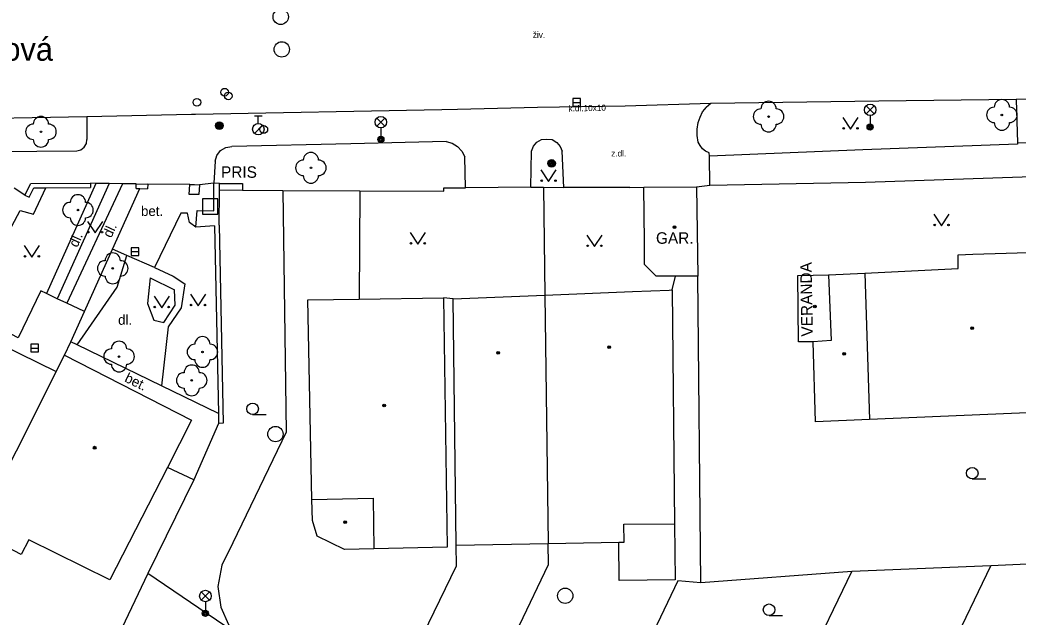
# Model space of a CAD drawing. Extents: x -600309 to -598967, y -1161267 to -1160292.
# Drawn here: x -599902.5 to -599837.4, y -1160659 to -1160620.1 of the extents above; entities that cross this region are included whole.
import ezdxf

# ---------------------------------------------------------------- set-up
doc = ezdxf.new("R2010")
doc.units = 0
for name, color, linetype in [('Level 10', 7, 'Continuous'), ('Level 11', 7, 'Continuous'), ('Level 22', 7, 'Continuous'), ('Level 24', 7, 'Continuous'), ('Level 25', 7, 'Continuous'), ('Level 26', 7, 'Continuous'), ('Level 27', 7, 'Continuous'), ('Level 28', 7, 'Continuous'), ('Level 33', 7, 'Continuous'), ('Level 36', 7, 'Continuous'), ('Level 39', 7, 'Continuous'), ('Level 40', 7, 'Continuous'), ('Level 41', 7, 'Continuous'), ('Level 42', 7, 'Continuous'), ('Level 49', 7, 'Continuous'), ('Level 5', 7, 'Continuous'), ('Level 7', 7, 'Continuous'), ('Level 8', 7, 'Continuous')]:
    doc.layers.add(name, color=color, linetype=linetype)

msp = doc.modelspace()

# ---------------------------------------------------------------- linework, layer by layer
at = {"layer": 'Level 10'}
for points in [[(-599831.42, -1160625.12), (-599837.52, -1160625.25), (-599846.47, -1160625.37), (-599857.43, -1160625.52), (-599863.01, -1160625.69), (-599868.73, -1160625.78)], [(-599868.73, -1160625.78), (-599873.94, -1160625.9), (-599874.9699, -1160625.92), (-599891.03, -1160626.23), (-599891.29, -1160626.24), (-599898.1, -1160626.39)], [(-599898.1, -1160626.39), (-599907.63, -1160626.56)]]:
    msp.add_lwpolyline(points, dxfattribs=at)
at = {"layer": 'Level 11'}
for points in [[(-599857.43, -1160625.52), (-599857.72, -1160625.77)], [(-599837.52, -1160625.25), (-599837.44, -1160628.07)], [(-599858.24, -1160626.76), (-599858.13, -1160626.4), (-599857.96, -1160626.06), (-599857.82, -1160625.89), (-599857.72, -1160625.77)], [(-599898.1, -1160626.39), (-599898.1, -1160627.86)], [(-599858.24, -1160628.03), (-599858.31, -1160627.61), (-599858.31, -1160627.18), (-599858.24, -1160626.76)], [(-599898.77, -1160628.61), (-599898.5, -1160628.54), (-599898.29, -1160628.37), (-599898.14, -1160628.13), (-599898.1, -1160627.86)], [(-599874.69, -1160627.99), (-599880.888, -1160628.141), (-599888.65, -1160628.33)], [(-599874.69, -1160627.99), (-599874.29, -1160628.1), (-599873.94, -1160628.32), (-599873.65, -1160628.62), (-599873.46, -1160628.99)], [(-599869.12, -1160628.62), (-599868.99, -1160628.3), (-599868.76, -1160628.04), (-599868.46, -1160627.87), (-599868.13, -1160627.8418), (-599867.77, -1160627.87), (-599867.4699, -1160628.05), (-599867.25, -1160628.31), (-599867.12, -1160628.63)], [(-599857.77, -1160628.63), (-599857.97, -1160628.47), (-599858.13, -1160628.26), (-599858.24, -1160628.03)], [(-599837.44, -1160628.16), (-599847.51, -1160628.53)], [(-599837.44, -1160628.07), (-599831.4, -1160627.92)], [(-599837.44, -1160628.07), (-599837.44, -1160628.16)], [(-599906.59, -1160628.67), (-599898.77, -1160628.61)], [(-599889.74, -1160629.28), (-599889.63, -1160628.9), (-599889.39, -1160628.58), (-599889.04, -1160628.38), (-599888.65, -1160628.33)], [(-599869.1599, -1160630.98), (-599869.12, -1160628.62)], [(-599867, -1160631), (-599867.12, -1160628.63)], [(-599857.54, -1160628.74), (-599857.77, -1160628.63)], [(-599857.52, -1160628.96), (-599857.54, -1160628.74)], [(-599847.51, -1160628.53), (-599857.52, -1160628.96)], [(-599889.74, -1160629.28), (-599889.84, -1160630.71)], [(-599873.42, -1160631.01), (-599873.46, -1160628.99)], [(-599857.48, -1160630.85), (-599857.52, -1160628.96)], [(-599897.52, -1160630.72), (-599900.74, -1160637.91)], [(-599896.66, -1160630.73), (-599900.04, -1160638.24)], [(-599895.78, -1160630.75), (-599899.42, -1160638.53)], [(-599890.8, -1160631.44), (-599891.44, -1160631.44), (-599891.4, -1160630.8), (-599891.09, -1160630.8), (-599890.76, -1160630.81)], [(-599890.76, -1160630.81), (-599890.8, -1160631.44)], [(-599905.95, -1160639.02), (-599902.45, -1160632.48), (-599901.58, -1160632.74), (-599900.78, -1160631.02)], [(-599899.56, -1160641.92), (-599899.16, -1160641.05), (-599898.27, -1160639.08), (-599896.43, -1160635.01), (-599894.65, -1160631.06)], [(-599885.33, -1160631.18), (-599885.12, -1160646.94), (-599888.59, -1160654.14)], [(-599880.3, -1160631.21), (-599880.36, -1160638.26)], [(-599891.01, -1160633.58), (-599891.41, -1160633.27), (-599891.54, -1160632.67), (-599891.98, -1160632.67), (-599893.7, -1160636.2), (-599892.49, -1160636.78), (-599891.71, -1160637.27), (-599891.95, -1160638.83), (-599892.8, -1160640.07), (-599893.25, -1160643.91)], [(-599895.51, -1160635.42), (-599896.43, -1160635.01)], [(-599898.74, -1160641.25), (-599896.14, -1160637.49), (-599895.51, -1160635.42)], [(-599893.7, -1160636.2), (-599895.51, -1160635.42)], [(-599893.99, -1160636.87), (-599894.16, -1160638.55), (-599893.74, -1160639.63), (-599893.08, -1160639.8), (-599892.34, -1160638.67), (-599892.4, -1160637.65)], [(-599893.99, -1160636.87), (-599892.4, -1160637.65)], [(-599859.95, -1160637.67), (-599859.72, -1160636.77)], [(-599900.74, -1160637.91), (-599901.12, -1160637.73), (-599902.59, -1160640.79), (-599905.95, -1160639.02)], [(-599900.04, -1160638.24), (-599900.74, -1160637.91)], [(-599899.42, -1160638.53), (-599900.04, -1160638.24)], [(-599898.27, -1160639.08), (-599899.42, -1160638.53)], [(-599874.23, -1160638.25), (-599874.86, -1160638.18)], [(-599898.74, -1160641.25), (-599899.16, -1160641.05)], [(-599893.25, -1160643.91), (-599898.74, -1160641.25)], [(-599889.53, -1160645.71), (-599893.25, -1160643.91)], [(-599889.52, -1160646.37), (-599891.14, -1160650.05), (-599892.86, -1160649.25)], [(-599859.79, -1160652.9099), (-599859.75, -1160656.56), (-599863.4, -1160656.6), (-599863.43, -1160654.1)], [(-599888.59, -1160654.14), (-599889.3, -1160655.61), (-599889.56, -1160656.99), (-599889.38, -1160658.34), (-599888.87, -1160659.48), (-599888.7199, -1160659.76)], [(-599851.77, -1160663.36), (-599851.2, -1160662.19), (-599848.23, -1160656.02)], [(-599844.52, -1160666.77), (-599839.1599, -1160655.64)]]:
    msp.add_lwpolyline(points, dxfattribs=at)
at = {"layer": 'Level 22'}
for centre in [(-599838.45, -1160626.26), (-599853.66, -1160626.37), (-599901.1, -1160627.36), (-599883.5, -1160629.71), (-599898.69, -1160632.46), (-599896.42, -1160636.26), (-599890.57, -1160641.71), (-599896.01, -1160642.01), (-599891.27, -1160643.56)]:
    msp.add_circle(centre, 0.05, dxfattribs=at)
for centre, start, end in [((-599853.66, -1160625.87), 0, 180), ((-599838.45, -1160625.76), 0, 180), ((-599854.16, -1160626.37), 90, 270), ((-599853.16, -1160626.37), 270, 90), ((-599838.95, -1160626.26), 90, 270), ((-599837.95, -1160626.26), 270, 90), ((-599901.6, -1160627.36), 90, 270), ((-599901.1, -1160626.86), 0, 180), ((-599900.6, -1160627.36), 270, 90), ((-599853.66, -1160626.87), 180, 0), ((-599838.45, -1160626.76), 180, 0), ((-599901.1, -1160627.86), 180, 0), ((-599883.5, -1160629.21), 0, 180), ((-599884, -1160629.71), 90, 270), ((-599883, -1160629.71), 270, 90), ((-599883.5, -1160630.21), 180, 0), ((-599898.69, -1160631.96), 0, 180), ((-599899.19, -1160632.46), 90, 270), ((-599898.19, -1160632.46), 270, 90), ((-599898.69, -1160632.96), 180, 0), ((-599896.42, -1160635.76), 0, 180), ((-599896.92, -1160636.26), 90, 270), ((-599895.92, -1160636.26), 270, 90), ((-599896.42, -1160636.76), 180, 0), ((-599896.01, -1160641.51), 0, 180), ((-599891.07, -1160641.71), 90, 270), ((-599890.57, -1160641.21), 0, 180), ((-599890.07, -1160641.71), 270, 90), ((-599896.51, -1160642.01), 90, 270), ((-599895.51, -1160642.01), 270, 90), ((-599896.01, -1160642.51), 180, 0), ((-599890.57, -1160642.21), 180, 0), ((-599891.77, -1160643.56), 90, 270), ((-599891.27, -1160643.06), 0, 180), ((-599890.77, -1160643.56), 270, 90), ((-599891.27, -1160644.06), 180, 0)]:
    msp.add_arc(centre, 0.5, start, end, dxfattribs=at)
at = {"layer": 'Level 24'}
for points in [[(-599889.46, -1160630.73), (-599887.97, -1160630.72)], [(-599889.45, -1160631.18), (-599889.46, -1160630.73)], [(-599887.97, -1160630.72), (-599887.96, -1160631.17)], [(-599887.96, -1160631.17), (-599889.45, -1160631.18)]]:
    msp.add_lwpolyline(points, dxfattribs=at)
at = {"layer": 'Level 25'}
for centre, radius in [((-599889.4699, -1160626.9699), 0.25), ((-599889.4699, -1160626.9699), 0.2), ((-599889.4699, -1160626.9699), 0.15), ((-599889.4699, -1160626.9699), 0.1), ((-599889.4699, -1160626.9699), 0.05), ((-599867.81, -1160629.42), 0.25), ((-599867.81, -1160629.42), 0.2), ((-599867.81, -1160629.42), 0.15), ((-599867.81, -1160629.42), 0.1), ((-599867.81, -1160629.42), 0.05)]:
    msp.add_circle(centre, radius, dxfattribs=at)
at = {"layer": 'Level 26'}
msp.add_lwpolyline([(-599890.57, -1160632.73), (-599889.57, -1160632.73), (-599889.57, -1160631.73), (-599890.57, -1160631.73)], close=True, dxfattribs=at)
at = {"layer": 'Level 27'}
for p, q in [((-599866.43, -1160625.45), (-599865.93, -1160625.45)), ((-599895.22, -1160635.17), (-599894.72, -1160635.17)), ((-599901.76, -1160641.46), (-599901.26, -1160641.46))]:
    msp.add_line(p, q, dxfattribs=at)
for points in [[(-599866.43, -1160625.7), (-599865.93, -1160625.7), (-599865.93, -1160625.2), (-599866.43, -1160625.2)], [(-599895.22, -1160635.42), (-599894.72, -1160635.42), (-599894.72, -1160634.92), (-599895.22, -1160634.92)], [(-599901.76, -1160641.71), (-599901.26, -1160641.71), (-599901.26, -1160641.21), (-599901.76, -1160641.21)]]:
    msp.add_lwpolyline(points, close=True, dxfattribs=at)
for centre in [(-599885.4699, -1160619.87), (-599885.4, -1160621.99), (-599885.81, -1160647.06), (-599866.92, -1160657.6)]:
    msp.add_circle(centre, 0.5, dxfattribs=at)
at = {"layer": 'Level 28'}
for p, q in [((-599887.188, -1160627.462), (-599886.658, -1160626.932)), ((-599887.18, -1160626.315), (-599886.68, -1160626.315)), ((-599886.93, -1160626.815), (-599886.93, -1160626.315))]:
    msp.add_line(p, q, dxfattribs=at)
for centre, radius in [((-599889.13, -1160624.78), 0.25), ((-599888.89, -1160625.02), 0.25), ((-599890.93, -1160625.44), 0.25), ((-599886.93, -1160627.19), 0.375), ((-599886.57, -1160627.21), 0.25)]:
    msp.add_circle(centre, radius, dxfattribs=at)
at = {"layer": 'Level 33'}
for p, q in [((-599847.305, -1160626.19), (-599846.775, -1160625.66)), ((-599847.305, -1160625.66), (-599846.775, -1160626.19)), ((-599879.205, -1160627), (-599878.675, -1160626.47)), ((-599879.205, -1160626.47), (-599878.675, -1160627)), ((-599847.04, -1160626.3), (-599847.04, -1160627.05)), ((-599878.94, -1160627.11), (-599878.94, -1160627.86)), ((-599890.645, -1160657.88), (-599890.115, -1160657.35)), ((-599890.645, -1160657.35), (-599890.115, -1160657.88)), ((-599890.38, -1160657.99), (-599890.38, -1160658.74))]:
    msp.add_line(p, q, dxfattribs=at)
for centre, radius in [((-599847.04, -1160625.925), 0.375), ((-599878.94, -1160626.735), 0.375), ((-599847.04, -1160627.05), 0.2), ((-599847.04, -1160627.05), 0.1445), ((-599847.04, -1160627.05), 0.0876), ((-599878.94, -1160627.86), 0.2), ((-599878.94, -1160627.86), 0.1445), ((-599878.94, -1160627.86), 0.0876), ((-599890.38, -1160657.615), 0.375), ((-599890.38, -1160658.74), 0.2), ((-599890.38, -1160658.74), 0.1445), ((-599890.38, -1160658.74), 0.0876)]:
    msp.add_circle(centre, radius, dxfattribs=at)
at = {"layer": 'Level 36'}
for p, q in [((-599887.3, -1160645.795), (-599886.425, -1160645.795)), ((-599840.38, -1160649.985), (-599839.505, -1160649.985)), ((-599853.63, -1160658.885), (-599852.755, -1160658.885))]:
    msp.add_line(p, q, dxfattribs=at)
for points in [[(-599848.81, -1160626.44), (-599848.31, -1160627.19), (-599847.81, -1160626.44)], [(-599868.5, -1160629.85), (-599868, -1160630.6), (-599867.5, -1160629.85)], [(-599842.88, -1160632.73), (-599842.38, -1160633.48), (-599841.88, -1160632.73)], [(-599898.07, -1160633.2), (-599897.57, -1160633.95), (-599897.07, -1160633.2)], [(-599877.03, -1160633.93), (-599876.53, -1160634.68), (-599876.03, -1160633.93)], [(-599865.51, -1160634.09), (-599865.01, -1160634.84), (-599864.51, -1160634.09)], [(-599902.19, -1160634.78), (-599901.69, -1160635.53), (-599901.19, -1160634.78)], [(-599891.36, -1160637.95), (-599890.86, -1160638.7), (-599890.36, -1160637.95)], [(-599893.73, -1160638.08), (-599893.23, -1160638.83), (-599892.73, -1160638.08)]]:
    msp.add_lwpolyline(points, dxfattribs=at)
for centre, radius in [((-599848.7602, -1160627.1398), 0.05), ((-599847.8608, -1160627.1398), 0.05), ((-599868.4502, -1160630.5498), 0.05), ((-599867.5508, -1160630.5498), 0.05), ((-599842.8302, -1160633.4298), 0.05), ((-599841.9308, -1160633.4298), 0.05), ((-599898.0202, -1160633.8998), 0.05), ((-599897.1208, -1160633.8998), 0.05), ((-599876.9802, -1160634.6298), 0.05), ((-599876.0808, -1160634.6298), 0.05), ((-599865.4602, -1160634.7898), 0.05), ((-599864.5608, -1160634.7898), 0.05), ((-599902.1402, -1160635.4798), 0.05), ((-599901.2408, -1160635.4798), 0.05), ((-599891.3102, -1160638.6498), 0.05), ((-599890.4108, -1160638.6498), 0.05), ((-599893.6802, -1160638.7798), 0.05), ((-599892.7808, -1160638.7798), 0.05), ((-599887.3001, -1160645.4199), 0.375), ((-599840.3801, -1160649.6099), 0.375), ((-599853.6301, -1160658.5099), 0.375)]:
    msp.add_circle(centre, radius, dxfattribs=at)
at = {"layer": 'Level 39'}
for centre, radius in [((-599859.79, -1160633.58), 0.09), ((-599859.79, -1160633.58), 0.0398), ((-599850.64, -1160638.75), 0.09), ((-599850.64, -1160638.75), 0.0398), ((-599840.39, -1160640.1599), 0.09), ((-599840.39, -1160640.1599), 0.0398), ((-599871.29, -1160641.76), 0.09), ((-599871.29, -1160641.76), 0.0398), ((-599864.05, -1160641.4), 0.09), ((-599864.05, -1160641.4), 0.0398), ((-599848.73, -1160641.83), 0.09), ((-599848.73, -1160641.83), 0.0398), ((-599878.73, -1160645.2), 0.09), ((-599878.73, -1160645.2), 0.0398), ((-599897.6, -1160647.95), 0.09), ((-599897.6, -1160647.95), 0.0398), ((-599881.27, -1160652.81), 0.09), ((-599881.27, -1160652.81), 0.0398)]:
    msp.add_circle(centre, radius, dxfattribs=at)
at = {"layer": 'Level 5'}
for points in [[(-599861.8, -1160630.98), (-599858.37, -1160630.95)], [(-599861.76, -1160634.51), (-599861.8, -1160630.98)], [(-599858.37, -1160630.95), (-599858.28, -1160636.76)], [(-599861.74, -1160636.02), (-599861.76, -1160634.51)], [(-599841.29, -1160635.39), (-599840.35, -1160635.34)], [(-599841.29, -1160636.28), (-599841.29, -1160635.39)], [(-599840.35, -1160635.34), (-599836, -1160635.2)], [(-599861, -1160636.77), (-599861.74, -1160636.02)], [(-599851.76, -1160636.73), (-599849.75, -1160636.68)], [(-599849.75, -1160636.68), (-599847.38, -1160636.57)], [(-599849.75, -1160636.68), (-599849.58, -1160640.9699)], [(-599847.38, -1160636.57), (-599841.29, -1160636.28)], [(-599847.38, -1160636.57), (-599847.09, -1160646.12)], [(-599860.19, -1160636.77), (-599861, -1160636.77)], [(-599858.28, -1160636.76), (-599859.72, -1160636.77), (-599860.19, -1160636.77)], [(-599851.7, -1160641.05), (-599851.76, -1160636.73)], [(-599868.24, -1160638.01), (-599862.54, -1160637.77)], [(-599862.54, -1160637.77), (-599860.15, -1160637.68)], [(-599860.15, -1160637.68), (-599859.95, -1160637.67)], [(-599859.95, -1160637.67), (-599859.79, -1160652.9099)], [(-599883.7, -1160638.31), (-599880.36, -1160638.26), (-599874.86, -1160638.18)], [(-599883.43, -1160651.33), (-599883.7, -1160638.31)], [(-599874.86, -1160638.18), (-599874.61, -1160654.44)], [(-599874.23, -1160638.25), (-599868.24, -1160638.01)], [(-599874.02, -1160654.3), (-599874.23, -1160638.25)], [(-599868.24, -1160638.01), (-599868.03, -1160654.19)], [(-599908.5, -1160638.88), (-599900.1, -1160642.99)], [(-599850.76, -1160641.05), (-599851.7, -1160641.05)], [(-599849.58, -1160640.9699), (-599850.76, -1160641.05)], [(-599850.6, -1160646.27), (-599850.76, -1160641.05)], [(-599900.1, -1160642.99), (-599899.56, -1160641.92)], [(-599899.56, -1160641.92), (-599891.28, -1160646.15)], [(-599900.1, -1160642.99), (-599905.35, -1160653.37)], [(-599831.65, -1160645.45), (-599847.09, -1160646.12)], [(-599891.28, -1160646.15), (-599892.86, -1160649.25), (-599896.6, -1160656.57)], [(-599847.09, -1160646.12), (-599850.6, -1160646.27)], [(-599883.43, -1160651.33), (-599879.45, -1160651.24)], [(-599883.4, -1160652.69), (-599883.43, -1160651.33)], [(-599879.45, -1160651.24), (-599879.4, -1160654.54)], [(-599883.09, -1160653.71), (-599883.4, -1160652.69)], [(-599863.09, -1160652.94), (-599859.79, -1160652.9099)], [(-599863.08, -1160654.1), (-599863.09, -1160652.94)], [(-599902.4, -1160654.92), (-599905.35, -1160653.37)], [(-599901.9, -1160653.95), (-599902.4, -1160654.92)], [(-599896.6, -1160656.57), (-599901.9, -1160653.95)], [(-599881.31, -1160654.58), (-599883.09, -1160653.71)], [(-599874.02, -1160654.3), (-599868.03, -1160654.19)], [(-599868.03, -1160654.19), (-599863.43, -1160654.1)], [(-599863.43, -1160654.1), (-599863.08, -1160654.1)], [(-599879.4, -1160654.54), (-599881.31, -1160654.58)], [(-599874.61, -1160654.44), (-599879.4, -1160654.54)]]:
    msp.add_lwpolyline(points, dxfattribs=at)
at = {"layer": 'Level 7'}
for points in [[(-599857.48, -1160630.85), (-599847.33, -1160630.65), (-599833.93, -1160630.18)], [(-599902.15, -1160631.5), (-599901.76, -1160630.72), (-599897.88, -1160630.71), (-599897.88, -1160631)], [(-599894.89, -1160631.06), (-599894.89, -1160630.76), (-599894.14, -1160630.77), (-599894.15, -1160631.07)], [(-599889.78, -1160633.48), (-599891.01, -1160633.58), (-599890.92, -1160632.5), (-599889.82, -1160632.51), (-599889.84, -1160630.71)], [(-599889.46, -1160630.73), (-599889.84, -1160630.71)], [(-599901.88, -1160631.63), (-599901.57, -1160631.02), (-599900.78, -1160631.02), (-599897.88, -1160631)], [(-599894.89, -1160631.06), (-599894.65, -1160631.06), (-599894.15, -1160631.07)], [(-599889.48, -1160633.44), (-599889.45, -1160631.18)], [(-599887.96, -1160631.17), (-599885.33, -1160631.18)], [(-599885.33, -1160631.18), (-599880.3, -1160631.21), (-599874.84, -1160631.24)], [(-599874.84, -1160631.24), (-599874.84, -1160631.02), (-599873.42, -1160631.01)], [(-599869.1599, -1160630.98), (-599868.33, -1160630.98)], [(-599868.33, -1160630.98), (-599868.24, -1160638.01)], [(-599868.33, -1160630.98), (-599867, -1160631)], [(-599862.7, -1160630.99), (-599861.8, -1160630.98)], [(-599858.37, -1160630.95), (-599857.48, -1160630.85)], [(-599902.15, -1160631.5), (-599901.88, -1160631.63)], [(-599889.48, -1160633.44), (-599889.22, -1160646.36), (-599889.52, -1160646.37)], [(-599889.48, -1160633.44), (-599889.22, -1160646.36), (-599889.52, -1160646.37)], [(-599889.78, -1160633.48), (-599889.53, -1160645.71), (-599889.52, -1160646.37)], [(-599858.07, -1160656.75), (-599858.28, -1160636.76)], [(-599891.14, -1160650.05), (-599894.14, -1160656.15)], [(-599873.69, -1160667.43), (-599868, -1160655.57), (-599868.03, -1160654.19)], [(-599878.35, -1160664.6), (-599874, -1160655.65), (-599874.02, -1160654.3)], [(-599820.94, -1160655.13), (-599830.09, -1160655.24), (-599839.1599, -1160655.64)], [(-599894.14, -1160656.15), (-599897.73, -1160663.7199)], [(-599888.7199, -1160659.76), (-599889.12, -1160659.55), (-599894.14, -1160656.15)], [(-599848.23, -1160656.02), (-599858.07, -1160656.75)], [(-599839.1599, -1160655.64), (-599848.23, -1160656.02)], [(-599858.07, -1160656.75), (-599859.57, -1160656.63), (-599866.18, -1160670.4699)]]:
    msp.add_lwpolyline(points, dxfattribs=at)
at = {"layer": 'Level 8'}
for points in [[(-599894.89, -1160630.76), (-599895.78, -1160630.75), (-599896.66, -1160630.73), (-599897.52, -1160630.72), (-599897.88, -1160630.71)], [(-599891.4, -1160630.8), (-599894.14, -1160630.77)], [(-599889.84, -1160630.71), (-599890.76, -1160630.81)], [(-599902.15, -1160631.5), (-599902.85, -1160631.03)], [(-599869.1599, -1160630.98), (-599873.42, -1160631.01)], [(-599862.7, -1160630.99), (-599867, -1160631)]]:
    msp.add_lwpolyline(points, dxfattribs=at)

# ---------------------------------------------------------------- texts
at = {"layer": 'Level 40'}
for s, height, p in [('živ.', 0.4, (-599869.03, -1160621.24)), ('z.dl.', 0.4, (-599863.92, -1160628.97)), ('bet.', 0.65, (-599894.58, -1160632.85)), ('dl.', 0.65, (-599896.07, -1160639.94))]:
    msp.add_text(s, height=height, dxfattribs=at).set_placement(p)
for s, height, rotation, p in [('k.dl.10x10', 0.4, 1.16, (-599866.7, -1160626.04)), ('dl.', 0.65, 65.821411, (-599898.73, -1160634.94)), ('dl.', 0.65, 64.842692, (-599896.52, -1160634.32)), ('bet.', 0.65, 333.950136, (-599895.7, -1160643.62))]:
    msp.add_text(s, height=height, rotation=rotation, dxfattribs=at).set_placement(p)
at = {"layer": 'Level 41'}
msp.add_text('GAR.', height=0.75, dxfattribs=at).set_placement((-599861, -1160634.66))
at = {"layer": 'Level 42'}
msp.add_text('PRIS', height=0.75, dxfattribs=at).set_placement((-599889.36, -1160630.36))
msp.add_text('VERANDA', height=0.75, rotation=91, dxfattribs=at).set_placement((-599850.77, -1160640.7))
at = {"layer": 'Level 49'}
msp.add_text('Lipová', height=1.5, dxfattribs=at).set_placement((-599906.23, -1160622.73))

doc.saveas('drawing.dxf')
